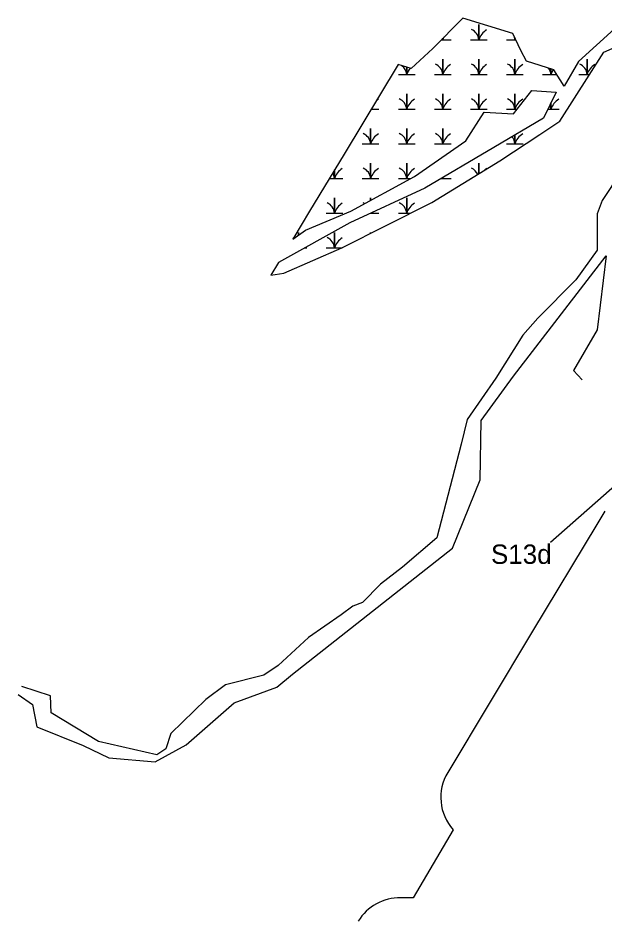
# Model space of a CAD drawing. Extents: x 1253697 to 1278588, y 912189 to 981699.
# Drawn here: x 1261708 to 1262313, y 919517 to 920449 of the extents above; entities that cross this region are included whole.
import ezdxf

# ---------------------------------------------------------------- set-up
doc = ezdxf.new("R2010")
doc.units = 0
for name, color, linetype in [('Default', 7, 'Continuous'), ('Exist Environmental Wetland Boundary', 7, 'Continuous'), ('Exist Hydro Jurisdictional Stream or Body of Water Mitigable', 7, 'Continuous'), ('Exist Hydro Jurisdictional Stream or Body of Water Mitigable Cogo Number', 7, 'Continuous')]:
    doc.layers.add(name, color=color, linetype=linetype)

msp = doc.modelspace()

# ---------------------------------------------------------------- linework, layer by layer
at = {"layer": 'Default'}
for p, q in [((1262256.85, 919908.33), (1262350.44, 919990.67)), ((1262238.52, 919816.27), (1262150.95, 919670.59)), ((1262238.52, 919816.27), (1262150.95, 919670.59)), ((1262238.52, 919816.27), (1262150.95, 919670.59)), ((1262238.52, 919816.27), (1262150.95, 919670.59))]:
    msp.add_line(p, q, dxfattribs=at)
for points in [[(1262313.07, 919940.3), (1262304.81, 919926.56), (1262238.52, 919816.27)], [(1262313.07, 919940.3), (1262304.81, 919926.56), (1262238.52, 919816.27)], [(1262313.07, 919940.3), (1262304.81, 919926.56), (1262238.52, 919816.27)], [(1262313.07, 919940.3), (1262304.81, 919926.56), (1262238.52, 919816.27)], [(1262156.48, 919611.56), (1262156.56, 919611.47), (1262115.35, 919541.12), (1262102.45, 919541.35)], [(1262156.48, 919611.56), (1262156.56, 919611.47), (1262115.35, 919541.12), (1262102.45, 919541.35)], [(1262156.48, 919611.56), (1262156.56, 919611.47), (1262115.35, 919541.12), (1262102.45, 919541.35)], [(1262156.48, 919611.56), (1262156.56, 919611.47), (1262115.35, 919541.12), (1262102.45, 919541.35)]]:
    msp.add_lwpolyline(points, dxfattribs=at)
for centre, start, end in [((1262355.92, 919914.54), 148.99047, 148.99059), ((1262355.92, 919914.54), 148.99047, 148.99059), ((1262281.37, 919790.51), 148.99057, 148.99059), ((1262281.37, 919790.51), 148.99057, 148.99059), ((1262193.8, 919644.83), 148.99059, 221.71181), ((1262193.8, 919644.83), 148.99059, 221.71181), ((1262193.8, 919644.83), 148.99059, 221.71181), ((1262193.8, 919644.83), 148.99059, 221.71181), ((1262101.55, 919491.36), 88.96897, 148.99067), ((1262101.55, 919491.36), 88.96897, 148.99067), ((1262101.55, 919491.36), 88.96897, 148.99067), ((1262101.55, 919491.36), 88.96897, 148.99067)]:
    msp.add_arc(centre, 50, start, end, dxfattribs=at)
at = {"layer": 'Exist Environmental Wetland Boundary'}
for p, q in [((1262072.16, 920355.06), (1262080.01, 920355.06)), ((1262174.41, 920283.5), (1262174.86, 920283.5)), ((1262071.59, 920247.72), (1262080.01, 920247.72)), ((1262003.66, 920211.94), (1262005.6, 920211.94))]:
    msp.add_line(p, q, dxfattribs=at)
for points in [[(1262323.08, 920437.77), (1262285.76, 920404), (1262270.98, 920378.79), (1262260.32, 920395.69), (1262232.05, 920404.59), (1262226.2, 920415.61), (1262217.93, 920432.9), (1262166.36, 920448.97), (1262135.52, 920417.71), (1262113.23, 920397.01), (1262099.85, 920400.9), (1262044.09, 920308.59), (1262008.44, 920249.56), (1261991.09, 920221.01), (1262004.4, 920230.17), (1262050.99, 920249.79), (1262116.55, 920285.64), (1262169.52, 920322.46), (1262188.58, 920351.85), (1262218.94, 920350.24), (1262237.68, 920374.14), (1262262.87, 920372.53), (1262249.8, 920345.75), (1262198.56, 920315.55), (1262127.21, 920273.48), (1262049.94, 920237.69), (1261976.33, 920196.72), (1261968.49, 920183.84), (1261981.82, 920185.76), (1262041.72, 920211.81), (1262134.39, 920258.82), (1262204.59, 920301.62), (1262245.88, 920328.88), (1262266.67, 920342.5), (1262311.78, 920413.74), (1262336.16, 920424.28)], [(1262174.41, 920426.62), (1262183.01, 920426.62), (1262183.01, 920442.4), (1262183.01, 920426.62), (1262191.62, 920426.62)], [(1262144.31, 920426.62), (1262145.81, 920426.62), (1262145.81, 920428.14)], [(1262145.81, 920428.14), (1262145.81, 920426.62), (1262154.41, 920426.62)], [(1262211.62, 920426.62), (1262220.22, 920426.62), (1262220.22, 920428.12)], [(1262220.22, 920428.12), (1262220.22, 920426.62), (1262220.93, 920426.62)], [(1262137.21, 920390.84), (1262145.81, 920390.84), (1262145.81, 920406.62), (1262145.81, 920390.84), (1262154.41, 920390.84)], [(1262174.41, 920390.84), (1262183.01, 920390.84), (1262183.01, 920406.62), (1262183.01, 920390.84), (1262191.62, 920390.84)], [(1262211.62, 920390.84), (1262220.22, 920390.84), (1262220.22, 920406.62), (1262220.22, 920390.84), (1262228.82, 920390.84)], [(1262286.02, 920390.84), (1262294.62, 920390.84), (1262294.62, 920406.62), (1262294.62, 920390.84), (1262297.28, 920390.84)], [(1262100.01, 920390.84), (1262108.61, 920390.84), (1262108.61, 920398.35)], [(1262108.61, 920398.35), (1262108.61, 920390.84), (1262117.21, 920390.84)], [(1262248.82, 920390.84), (1262257.42, 920390.84), (1262257.42, 920396.6)], [(1262257.42, 920396.6), (1262257.42, 920390.84), (1262263.38, 920390.84)], [(1262100.01, 920355.06), (1262108.61, 920355.06), (1262108.61, 920370.84), (1262108.61, 920355.06), (1262117.21, 920355.06)], [(1262137.21, 920355.06), (1262145.81, 920355.06), (1262145.81, 920370.84), (1262145.81, 920355.06), (1262154.41, 920355.06)], [(1262174.41, 920355.06), (1262183.01, 920355.06), (1262183.01, 920370.84), (1262183.01, 920355.06), (1262191.62, 920355.06)], [(1262211.62, 920355.06), (1262220.22, 920355.06), (1262220.22, 920370.84), (1262220.22, 920355.06), (1262222.72, 920355.06)], [(1262254.34, 920355.06), (1262257.42, 920355.06), (1262257.42, 920361.37)], [(1262257.42, 920361.37), (1262257.42, 920355.06), (1262266.02, 920355.06)], [(1262062.8, 920319.28), (1262071.4, 920319.28), (1262071.4, 920335.06), (1262071.4, 920319.28), (1262080.01, 920319.28)], [(1262100.01, 920319.28), (1262108.61, 920319.28), (1262108.61, 920335.06), (1262108.61, 920319.28), (1262117.21, 920319.28)], [(1262137.21, 920319.28), (1262145.81, 920319.28), (1262145.81, 920335.06), (1262145.81, 920319.28), (1262154.41, 920319.28)], [(1262211.62, 920319.28), (1262220.22, 920319.28), (1262220.22, 920328.32)], [(1262220.22, 920328.32), (1262220.22, 920319.28), (1262228.82, 920319.28)], [(1262028.93, 920283.5), (1262034.2, 920283.5), (1262034.2, 920292.22)], [(1262034.2, 920292.22), (1262034.2, 920283.5), (1262042.8, 920283.5)], [(1262062.8, 920283.5), (1262071.4, 920283.5), (1262071.4, 920299.28), (1262071.4, 920283.5), (1262080.01, 920283.5)], [(1262100.01, 920283.5), (1262108.61, 920283.5), (1262108.61, 920299.28), (1262108.61, 920283.5), (1262112.63, 920283.5)], [(1262183.01, 920288.47), (1262183.01, 920299.28), (1262183.01, 920288.47)], [(1262144.19, 920283.5), (1262145.81, 920283.5), (1262145.81, 920284.45)], [(1262145.81, 920284.45), (1262145.81, 920283.5), (1262154.41, 920283.5)], [(1262025.6, 920247.72), (1262034.2, 920247.72), (1262034.2, 920263.5), (1262034.2, 920247.72), (1262042.8, 920247.72)], [(1262071.4, 920260.95), (1262071.4, 920263.5), (1262071.4, 920260.95)], [(1262100.01, 920247.72), (1262108.61, 920247.72), (1262108.61, 920263.5), (1262108.61, 920247.72), (1262112.5, 920247.72)], [(1261997, 920225.08), (1261997, 920227.72), (1261997, 920225.08)], [(1262025.6, 920211.94), (1262034.2, 920211.94), (1262034.2, 920227.72), (1262034.2, 920211.94), (1262041.98, 920211.94)], [(1262071.4, 920226.87), (1262071.4, 920227.72), (1262071.4, 920226.87)]]:
    msp.add_lwpolyline(points, dxfattribs=at)
for centre, radius, start, end in [((1262170.75, 920425.73), 12.3, 4.14034, 67.53497), ((1262201.26, 920420.56), 19.22, 122.12745, 161.62219), ((1262133.54, 920425.73), 12.3, 4.14034, 10.4694), ((1262164.05, 920420.56), 19.22, 153.10082, 161.62219), ((1262207.95, 920425.73), 12.3, 4.14034, 15.13619), ((1262238.46, 920420.56), 19.22, 158.91123, 161.62219), ((1262096.34, 920389.95), 12.3, 4.14034, 52.90552), ((1262126.85, 920384.78), 19.22, 139.38164, 161.62219), ((1262133.54, 920389.95), 12.3, 4.14034, 67.53497), ((1262164.05, 920384.78), 19.22, 122.12745, 161.62219), ((1262170.75, 920389.95), 12.3, 4.14034, 67.53497), ((1262201.26, 920384.78), 19.22, 122.12745, 161.62219), ((1262207.95, 920389.95), 12.3, 4.14034, 67.53497), ((1262238.46, 920384.78), 19.22, 122.12745, 161.62219), ((1262245.15, 920389.95), 12.3, 4.14034, 37.15386), ((1262275.66, 920384.78), 19.22, 144.95825, 161.62219), ((1262282.36, 920389.95), 12.3, 4.14034, 67.53497), ((1262312.87, 920384.78), 19.22, 122.12745, 161.62219), ((1262089.65, 920349), 19.22, 122.12745, 129.21917), ((1262096.34, 920354.17), 12.3, 4.14034, 67.53497), ((1262126.85, 920349), 19.22, 122.12745, 161.62219), ((1262133.54, 920354.17), 12.3, 4.14034, 67.53497), ((1262164.05, 920349), 19.22, 122.12745, 161.62219), ((1262170.75, 920354.17), 12.3, 4.14034, 67.53497), ((1262201.26, 920349), 19.22, 122.12745, 161.62219), ((1262207.95, 920354.17), 12.3, 4.14034, 67.53497), ((1262238.46, 920349), 19.22, 122.12745, 161.62219), ((1262275.66, 920349), 19.22, 122.12745, 161.62219), ((1262245.15, 920354.17), 12.3, 4.14034, 24.22184), ((1262059.14, 920318.39), 12.3, 4.14034, 67.53497), ((1262089.65, 920313.22), 19.22, 122.12745, 161.62219), ((1262096.34, 920318.39), 12.3, 4.14034, 67.53497), ((1262126.85, 920313.22), 19.22, 122.12745, 161.62219), ((1262133.54, 920318.39), 12.3, 4.14034, 67.53497), ((1262164.05, 920313.22), 19.22, 122.12745, 161.62219), ((1262238.46, 920313.22), 19.22, 122.12745, 161.62219), ((1262207.95, 920318.39), 12.3, 4.14034, 41.39908), ((1262052.44, 920277.44), 19.22, 122.12745, 161.62219), ((1262059.14, 920282.61), 12.3, 4.14034, 67.53497), ((1262089.65, 920277.44), 19.22, 122.12745, 161.62219), ((1262096.34, 920282.61), 12.3, 4.14034, 67.53497), ((1262126.85, 920277.44), 19.22, 122.12745, 161.62219), ((1262170.75, 920282.61), 12.3, 24.92017, 67.53497), ((1262201.26, 920277.44), 19.22, 122.12745, 131.59973), ((1262021.93, 920282.61), 12.3, 4.14034, 32.13553), ((1262133.54, 920282.61), 12.3, 4.14034, 8.34205), ((1262164.05, 920277.44), 19.22, 157.74205, 161.62219), ((1262021.93, 920246.83), 12.3, 4.14034, 67.53497), ((1262052.44, 920241.66), 19.22, 122.12745, 161.62219), ((1262059.14, 920246.83), 12.3, 60.62082, 67.53497), ((1262096.34, 920246.83), 12.3, 4.14034, 67.53497), ((1262126.85, 920241.66), 19.22, 122.12745, 161.62219), ((1261984.73, 920211.05), 12.3, 56.51011, 57.50688), ((1262021.93, 920211.05), 12.3, 4.14034, 67.53497), ((1262052.44, 920205.88), 19.22, 122.12745, 161.62219)]:
    msp.add_arc(centre, radius, start, end, dxfattribs=at)
at = {"layer": 'Exist Hydro Jurisdictional Stream or Body of Water Mitigable'}
for points in [[(1262366.23, 920345.43), (1262310.25, 920260.86), (1262304.89, 920247.01), (1262304.89, 920209.43), (1262283.19, 920178.79), (1262243.99, 920139.21), (1262228.56, 920121.64), (1262200.41, 920077.36), (1262170.91, 920034.93), (1262164.74, 920009.35), (1262139.87, 919912.85)], [(1261707.86, 919750.99), (1261722.6, 919740.83), (1261727.11, 919717.61), (1261775.13, 919698.48), (1261801.62, 919685.62), (1261849.32, 919681.68), (1261881.22, 919699.02), (1261930.72, 919742.46), (1261974.62, 919758.72), (1261990.78, 919772.17), (1262155.95, 919901.9), (1262184.41, 919972.46), (1262185.47, 920033.7), (1262218.84, 920079.65), (1262314.45, 920203.65)], [(1262314.45, 920203.65), (1262305.13, 920127.25), (1262280.52, 920085.3), (1262289.72, 920075.77)], [(1262139.87, 919912.85), (1262104.33, 919882.6), (1262081.74, 919864.8), (1262063.13, 919846.04), (1262053.24, 919842.35), (1262041.08, 919833.18), (1262007.39, 919809.93), (1261976.14, 919780.91), (1261961.44, 919770.94), (1261921.79, 919760.97), (1261901.54, 919745.85), (1261865.48, 919710.76), (1261860.23, 919694.94), (1261850.86, 919688.87), (1261790.73, 919702.71), (1261741.9, 919732.26), (1261741.17, 919749.73), (1261711.6, 919759.26)]]:
    msp.add_lwpolyline(points, dxfattribs=at)

# ---------------------------------------------------------------- texts
at = {"layer": 'Exist Hydro Jurisdictional Stream or Body of Water Mitigable Cogo Number'}
msp.add_text('S13d', height=20, dxfattribs=at).set_placement((1262195.59, 919885.82))

doc.saveas('drawing.dxf')
